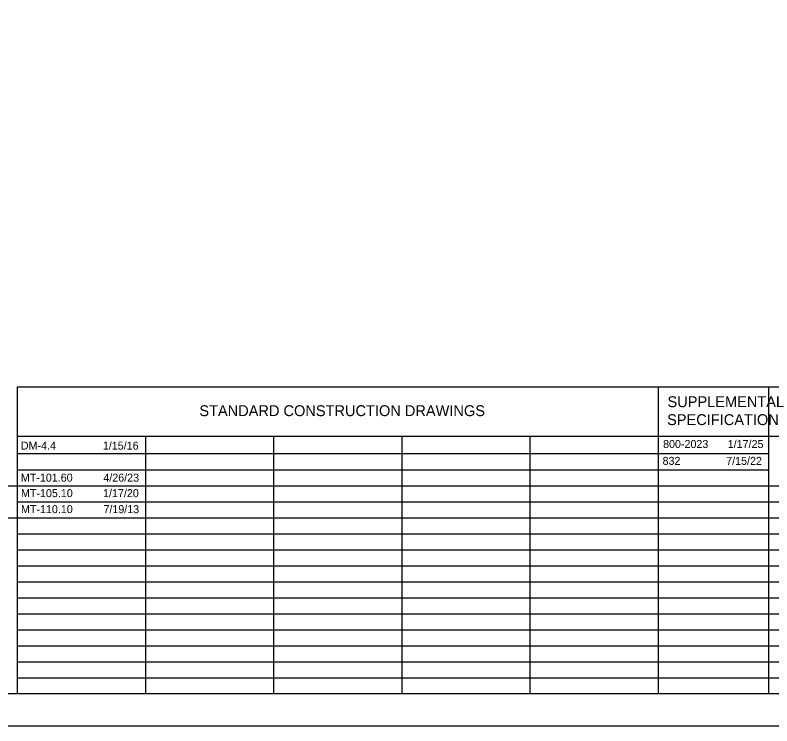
# Model space of a CAD drawing. Extents: x 0 to 81.5, y 0 to 35.2.
# Drawn here: x 10.11 to 21.92, y 0 to 11.1 of the extents above; entities that cross this region are included whole.
import ezdxf

# ---------------------------------------------------------------- set-up
doc = ezdxf.new("R2010")
doc.units = 0
for name, color, linetype in [('SH_Border', 7, 'Continuous'), ('SH_Cut_Line', 7, 'Continuous'), ('SH_Data', 7, 'Continuous'), ('SH_Text', 7, 'Continuous')]:
    doc.layers.add(name, color=color, linetype=linetype)

msp = doc.modelspace()

# ---------------------------------------------------------------- linework, layer by layer
at = {"layer": 'SH_Border'}
msp.add_lwpolyline([(1.5, 21.5), (33.5, 21.5), (33.5, 0.5), (1.5, 0.5)], close=True, dxfattribs=at)
at = {"layer": 'SH_Cut_Line'}
msp.add_lwpolyline([(0, 0), (34, 0), (34, 22), (0, 22)], close=True, dxfattribs=at)
at = {"layer": 'SH_Data'}
for p, q in [((10.15, 5.292), (23.6, 5.292)), ((10.15, 0.5), (10.15, 5.292)), ((20.15, 0.5), (20.15, 5.292)), ((21.875, 0.5), (21.875, 5.292)), ((10.15, 4.521), (23.6, 4.521)), ((12.15, 0.5), (12.15, 4.521)), ((14.15, 0.5), (14.15, 4.521)), ((16.15, 0.5), (16.15, 4.521)), ((18.15, 0.5), (18.15, 4.521)), ((10.15, 4.25), (21.875, 4.25)), ((10.15, 4), (21.875, 4)), ((7.35, 3.75), (10.15, 3.75)), ((10.15, 3.75), (23.6, 3.75)), ((10.15, 0.5), (10.15, 3.75)), ((10.15, 3.5), (23.6, 3.5)), ((7.35, 3.25), (10.15, 3.25)), ((10.15, 3.25), (23.6, 3.25)), ((10.15, 3), (23.6, 3)), ((10.15, 2.75), (23.6, 2.75)), ((10.15, 2.5), (23.6, 2.5)), ((10.15, 2.25), (23.6, 2.25)), ((10.15, 2), (23.6, 2)), ((10.15, 1.75), (23.6, 1.75)), ((10.15, 1.5), (23.6, 1.5)), ((10.15, 1.25), (23.6, 1.25)), ((10.15, 1), (23.6, 1)), ((10.15, 0.75), (23.6, 0.75))]:
    msp.add_line(p, q, dxfattribs=at)

# ---------------------------------------------------------------- texts
at = {"layer": 'SH_Text'}
for s, height, p in [('SUPPLEMENTAL', 0.17, (20.293, 4.976)), ('STANDARD CONSTRUCTION DRAWINGS', 0.17, (12.986, 4.836)), ('SPECIFICATIONS', 0.17, (20.287, 4.696)), ('DM-4.4', 0.125, (10.2, 4.313)), ('1/15/16', 0.125, (11.48, 4.313)), ('800-2023', 0.125, (20.224, 4.338)), ('1/17/25', 0.125, (21.233, 4.338)), ('832', 0.125, (20.216, 4.075)), ('7/15/22', 0.125, (21.209, 4.075)), ('MT-101.60', 0.125, (10.2, 3.813)), ('4/26/23', 0.125, (11.487, 3.813)), ('MT-105.10', 0.125, (10.202, 3.571)), ('1/17/20', 0.125, (11.483, 3.571)), ('MT-110.10', 0.125, (10.202, 3.321)), ('7/19/13', 0.125, (11.489, 3.321))]:
    msp.add_text(s, height=height, dxfattribs=at).set_placement(p)

doc.saveas('drawing.dxf')
